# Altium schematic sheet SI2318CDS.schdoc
size 127 x 101 mm
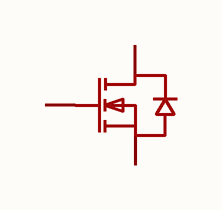
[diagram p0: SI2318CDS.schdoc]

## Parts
Q?  si2318cds  [SOT-23-3_L2.9-W1.3-P0.95-LS2.4-BR]  (value not drawn)

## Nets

Not connected (* = marked no-connect by the designer): Q? 1(G) 2(S) 3(D)

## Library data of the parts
Q? = si2318cds: 数量:1个N沟道;漏源电压(Vdss):40V;连续漏极电流(Id):3.9A;导通电阻(RDS(on)):50mΩ@4.5V;耗散功率(Pd):1.25W;阈值电压(Vgs(th)):3V;; Manufacturer: TECH PUBLIC(台舟); AddInBom: yes; ModelId: c62791f0466c4ae2a892c056b845b0ca; ModelName: SOT-23-3P_L2.9-W1.3-H1.0-LS2.4-P0.95; ModelTransform: 98.425,114.173,0,180,0,0,0.0005,-0.0005,0; Number: 1个N沟道; Drain to Source Voltage: 40V; Current - Continuous Drain(Id): 3.9A; Pd - Power Dissipation: 1.25W; Gate Threshold Voltage (Vgs(th)): 3V; Gate Charge(Qg): 10nC@10V; Input Capacitance(Ciss): 540pF; Reverse Transfer Capacitance (Crss@Vds): 45pF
